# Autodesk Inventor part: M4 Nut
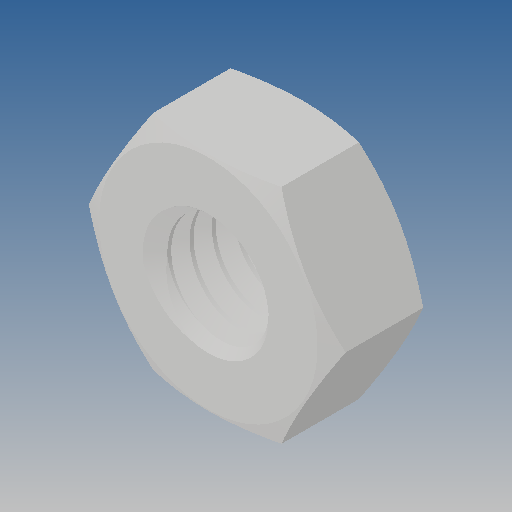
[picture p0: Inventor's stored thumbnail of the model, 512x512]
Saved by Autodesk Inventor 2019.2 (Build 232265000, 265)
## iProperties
Created: 2012-09
Part Number: M4 Nut
Material: Ogólny
Document SubType Name: Modeling
Designer: CADENGINEERING4
Density: 1 g/cm^3
Appearance: Domyślna
Author: CADENGINEERING4
Revision Number: ÈÎºÎ
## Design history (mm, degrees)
feature "ÇÐ³ý-É¨Ãè1"
node "Bryła1"
